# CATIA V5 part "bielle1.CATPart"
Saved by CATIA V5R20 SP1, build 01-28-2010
Part number: bielle1
Bounding box of the stored display mesh (mm): x -105.167 to -41.167, y 0 to 10, z 48.093 to 61.907
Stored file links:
  E:\EDELI\gcausse\Edeli_2012_233_gcausse\bielle1.CATPart
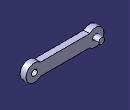
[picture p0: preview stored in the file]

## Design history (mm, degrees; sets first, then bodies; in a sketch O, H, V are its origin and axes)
Body1 (main body)
  Sketch1 on zx-plane, origin (0, 0, 0), H (-1, 0, 0), V (0, 0, 1)
    line L1 (93.2678, 60) -> (53.0657, 60)
    line L2 (93.2678, 50) -> (53.0657, 50)
    arc A1 centre (98.1667, 55) radius 7 from (93.2678, 60) to (93.2678, 50) cw
    point P5 (98.1667, 55)
    arc A2 centre (48.1667, 55) radius 7 from (53.0657, 60) to (53.0657, 50) ccw
    point P6 (48.1667, 55)
    circle A3 centre (48.1667, 55) radius 2.5
    radius A2 = 7
    radius A1 = 7
    distance L1 L2 = 10
    distance P6 L1 = 5
    distance P5 L1 = 5
    distance P6 P5 = 50
    radius A3 = 2.5
    horizontal: L1 H, L2 H
  Pad1: profile Sketch1, direction (0, 1, 0), length 5
  Sketch2 on end face of Pad1, origin (0, 5, 0), H (-1, 0, 0), V (0, 0, 1)
    circle A1 centre (98.1667, 55) radius 2.5
    reference projected arc E1 centre (98.1667, 55) radius 7 from (93.2678, 50) to (93.2678, 60) ccw from edge [face of Pad1 from Sketch1.A1 | end face of Pad1]
    reference projected arc E2 centre (98.1667, 55) radius 7 from (93.2678, 50) to (93.2678, 60) ccw from edge [face of Pad1 from Sketch1.A1 | end face of Pad1]
    radius A1 = 2.5
    radius E2 = 7 (reference)
    concentricity: A1 E1
  Pad2: profile Sketch2, direction (0, 1, 0), length 5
